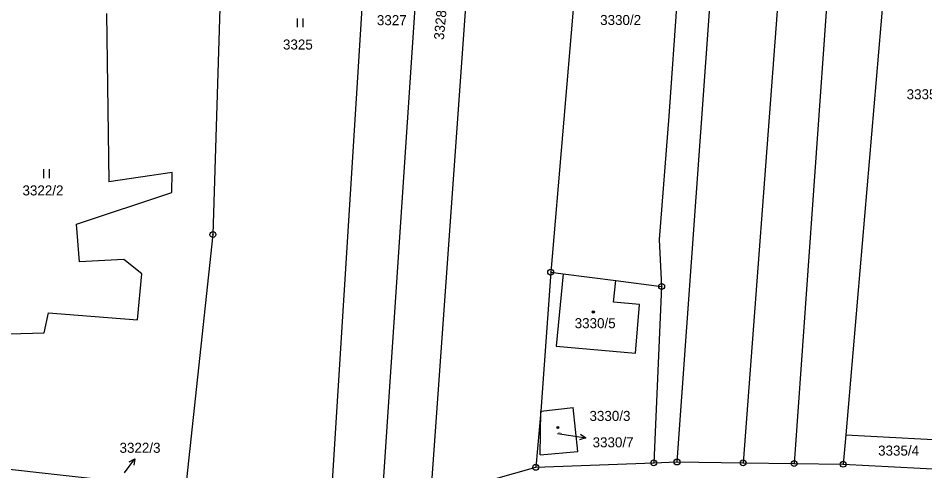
# Model space of a CAD drawing. Extents: x -593183 to -588034, y -1130415 to -1124994.
# Drawn here: x -592484.2 to -592330.3, y -1128423.8 to -1128347 of the extents above; entities that cross this region are included whole.
import ezdxf

# ---------------------------------------------------------------- set-up
doc = ezdxf.new("R2010")
doc.units = 0
for name, color, linetype in [('Vrstva 1', 7, 'Continuous'), ('Vrstva 16', 7, 'Continuous'), ('Vrstva 18', 7, 'Continuous'), ('Vrstva 19', 7, 'Continuous'), ('Vrstva 24', 7, 'Continuous'), ('Vrstva 25', 7, 'Continuous')]:
    doc.layers.add(name, color=color, linetype=linetype)

msp = doc.modelspace()

# ---------------------------------------------------------------- linework, layer by layer
at = {"layer": 'Vrstva 1'}
for p, q in [((-592361.55, -1128271.48), (-592372.37, -1128422.32)), ((-592349.93, -1128273.12), (-592361.14, -1128422.47)), ((-592341.97, -1128273.51), (-592352.48, -1128422.59)), ((-592384.86, -1128285.14), (-592393.8, -1128390.13)), ((-592334.21, -1128306.65), (-592343.73, -1128417.73)), ((-592370.08, -1128310.56), (-592373.76, -1128363.68)), ((-592449.76, -1128338.03), (-592451.14, -1128383.75)), ((-592425.44, -1128338.73), (-592431.29, -1128432.06)), ((-592416.42, -1128338.98), (-592422.59, -1128430.59)), ((-592407.84, -1128339.23), (-592414.19, -1128428.23)), ((-592469.19, -1128346.27), (-592468.8, -1128374.79)), ((-592373.76, -1128363.68), (-592375.38, -1128384.6)), ((-592458.07, -1128373.2), (-592468.8, -1128374.79)), ((-592458.13, -1128376.6), (-592458.07, -1128373.2)), ((-592474.3, -1128381.97), (-592458.13, -1128376.6)), ((-592473.8, -1128388.38), (-592474.3, -1128381.97)), ((-592451.14, -1128383.75), (-592455.76, -1128426.89)), ((-592375.38, -1128384.6), (-592374.97, -1128392.55)), ((-592466.25, -1128387.98), (-592473.8, -1128388.38)), ((-592463.18, -1128390.4), (-592466.25, -1128387.98)), ((-592463.92, -1128398.23), (-592463.18, -1128390.4)), ((-592393.8, -1128390.13), (-592395.46, -1128413.7)), ((-592393.8, -1128390.13), (-592391.66, -1128390.41)), ((-592391.66, -1128390.41), (-592392.9, -1128402.66)), ((-592391.66, -1128390.41), (-592382.75, -1128391.54)), ((-592383.13, -1128395.21), (-592382.75, -1128391.54)), ((-592382.75, -1128391.54), (-592374.97, -1128392.55)), ((-592374.97, -1128392.55), (-592376.31, -1128422.47)), ((-592378.72, -1128395.63), (-592383.13, -1128395.21)), ((-592379.39, -1128403.88), (-592378.72, -1128395.63)), ((-592479.76, -1128400.42), (-592479.06, -1128397.04)), ((-592479.06, -1128397.04), (-592463.92, -1128398.23)), ((-592490.55, -1128400.75), (-592479.76, -1128400.42)), ((-592392.9, -1128402.66), (-592379.39, -1128403.88)), ((-592395.46, -1128413.7), (-592390, -1128413.11)), ((-592389.21, -1128420.52), (-592390, -1128413.11)), ((-592395.46, -1128413.7), (-592396.34, -1128423.23)), ((-592395.57, -1128421.12), (-592395.46, -1128413.7)), ((-592343.73, -1128417.73), (-592344.16, -1128422.71)), ((-592343.73, -1128417.73), (-592322.67, -1128418.86)), ((-592395.57, -1128421.12), (-592389.21, -1128420.52)), ((-592492.8, -1128422.75), (-592455.76, -1128426.89)), ((-592396.34, -1128423.23), (-592376.31, -1128422.47)), ((-592376.31, -1128422.47), (-592372.37, -1128422.32)), ((-592372.37, -1128422.32), (-592361.14, -1128422.47)), ((-592361.14, -1128422.47), (-592352.48, -1128422.59)), ((-592352.48, -1128422.59), (-592344.16, -1128422.71)), ((-592344.16, -1128422.71), (-592323.42, -1128423.8)), ((-592414.19, -1128428.23), (-592396.34, -1128423.23))]:
    msp.add_line(p, q, dxfattribs=at)
at = {"layer": 'Vrstva 16'}
msp.add_line((-592392.66, -1128417.5), (-592390.79, -1128417.78), dxfattribs=at)
at = {"layer": 'Vrstva 24'}
for centre, radius in [((-592451.14, -1128383.75), 0.5), ((-592451.14, -1128383.75), 0.0327), ((-592393.8, -1128390.13), 0.5), ((-592393.8, -1128390.13), 0.0327), ((-592374.97, -1128392.55), 0.5), ((-592374.97, -1128392.55), 0.0327), ((-592396.34, -1128423.23), 0.5), ((-592376.31, -1128422.47), 0.5), ((-592376.31, -1128422.47), 0.0327), ((-592372.37, -1128422.32), 0.5), ((-592372.37, -1128422.32), 0.0327), ((-592361.14, -1128422.47), 0.5), ((-592361.14, -1128422.47), 0.0327), ((-592352.48, -1128422.59), 0.5), ((-592352.48, -1128422.59), 0.0327), ((-592344.16, -1128422.71), 0.5), ((-592344.16, -1128422.71), 0.0327), ((-592396.34, -1128423.23), 0.0327)]:
    msp.add_circle(centre, radius, dxfattribs=at)
at = {"layer": 'Vrstva 25'}
for p, q in [((-592436.82, -1128347.08), (-592436.82, -1128348.58)), ((-592435.8, -1128348.58), (-592435.8, -1128347.08)), ((-592479.88, -1128372.68), (-592479.88, -1128374.18)), ((-592478.85, -1128374.18), (-592478.85, -1128372.68)), ((-592390.79, -1128417.78), (-592387.82, -1128418.23)), ((-592466.14, -1128424.19), (-592464.36, -1128421.78))]:
    msp.add_line(p, q, dxfattribs=at)
for points in [[(-592388.74, -1128417.59), (-592387.82, -1128418.23), (-592388.89, -1128418.57)], [(-592465.35, -1128422.28), (-592464.36, -1128421.78), (-592464.55, -1128422.88)]]:
    msp.add_lwpolyline(points, dxfattribs=at)
for centre, radius in [((-592386.57, -1128396.88), 0.175), ((-592386.57, -1128396.88), 0.15), ((-592392.6, -1128416.46), 0.175), ((-592392.6, -1128416.46), 0.15)]:
    msp.add_circle(centre, radius, dxfattribs=at)

# ---------------------------------------------------------------- texts
at = {"layer": 'Vrstva 16'}
for s, p in [('3335/2', (-592333.39, -1128360.8)), ('3330/7', (-592386.69, -1128419.84)), ('3322/3', (-592466.98, -1128420.77))]:
    msp.add_text(s, height=1.7, dxfattribs=at).set_placement(p)
at = {"layer": 'Vrstva 18'}
msp.add_text('3328/2', height=1.7, rotation=84.785, dxfattribs=at).set_placement((-592411.94, -1128350.79))
for s, p in [('3327', (-592423.3, -1128348.23)), ('3330/2', (-592385.41, -1128348.2)), ('3325', (-592439.24, -1128352.36)), ('3322/2', (-592483.45, -1128377.11)), ('3330/3', (-592387.22, -1128415.36)), ('3335/4', (-592338.23, -1128421.24))]:
    msp.add_text(s, height=1.7, dxfattribs=at).set_placement(p)
at = {"layer": 'Vrstva 19'}
for s, height, p in [('3330/5', 1.7, (-592389.73, -1128399.63)), ('3330/7', 0.2, (-592392.66, -1128417.5))]:
    msp.add_text(s, height=height, dxfattribs=at).set_placement(p)

doc.saveas('drawing.dxf')
